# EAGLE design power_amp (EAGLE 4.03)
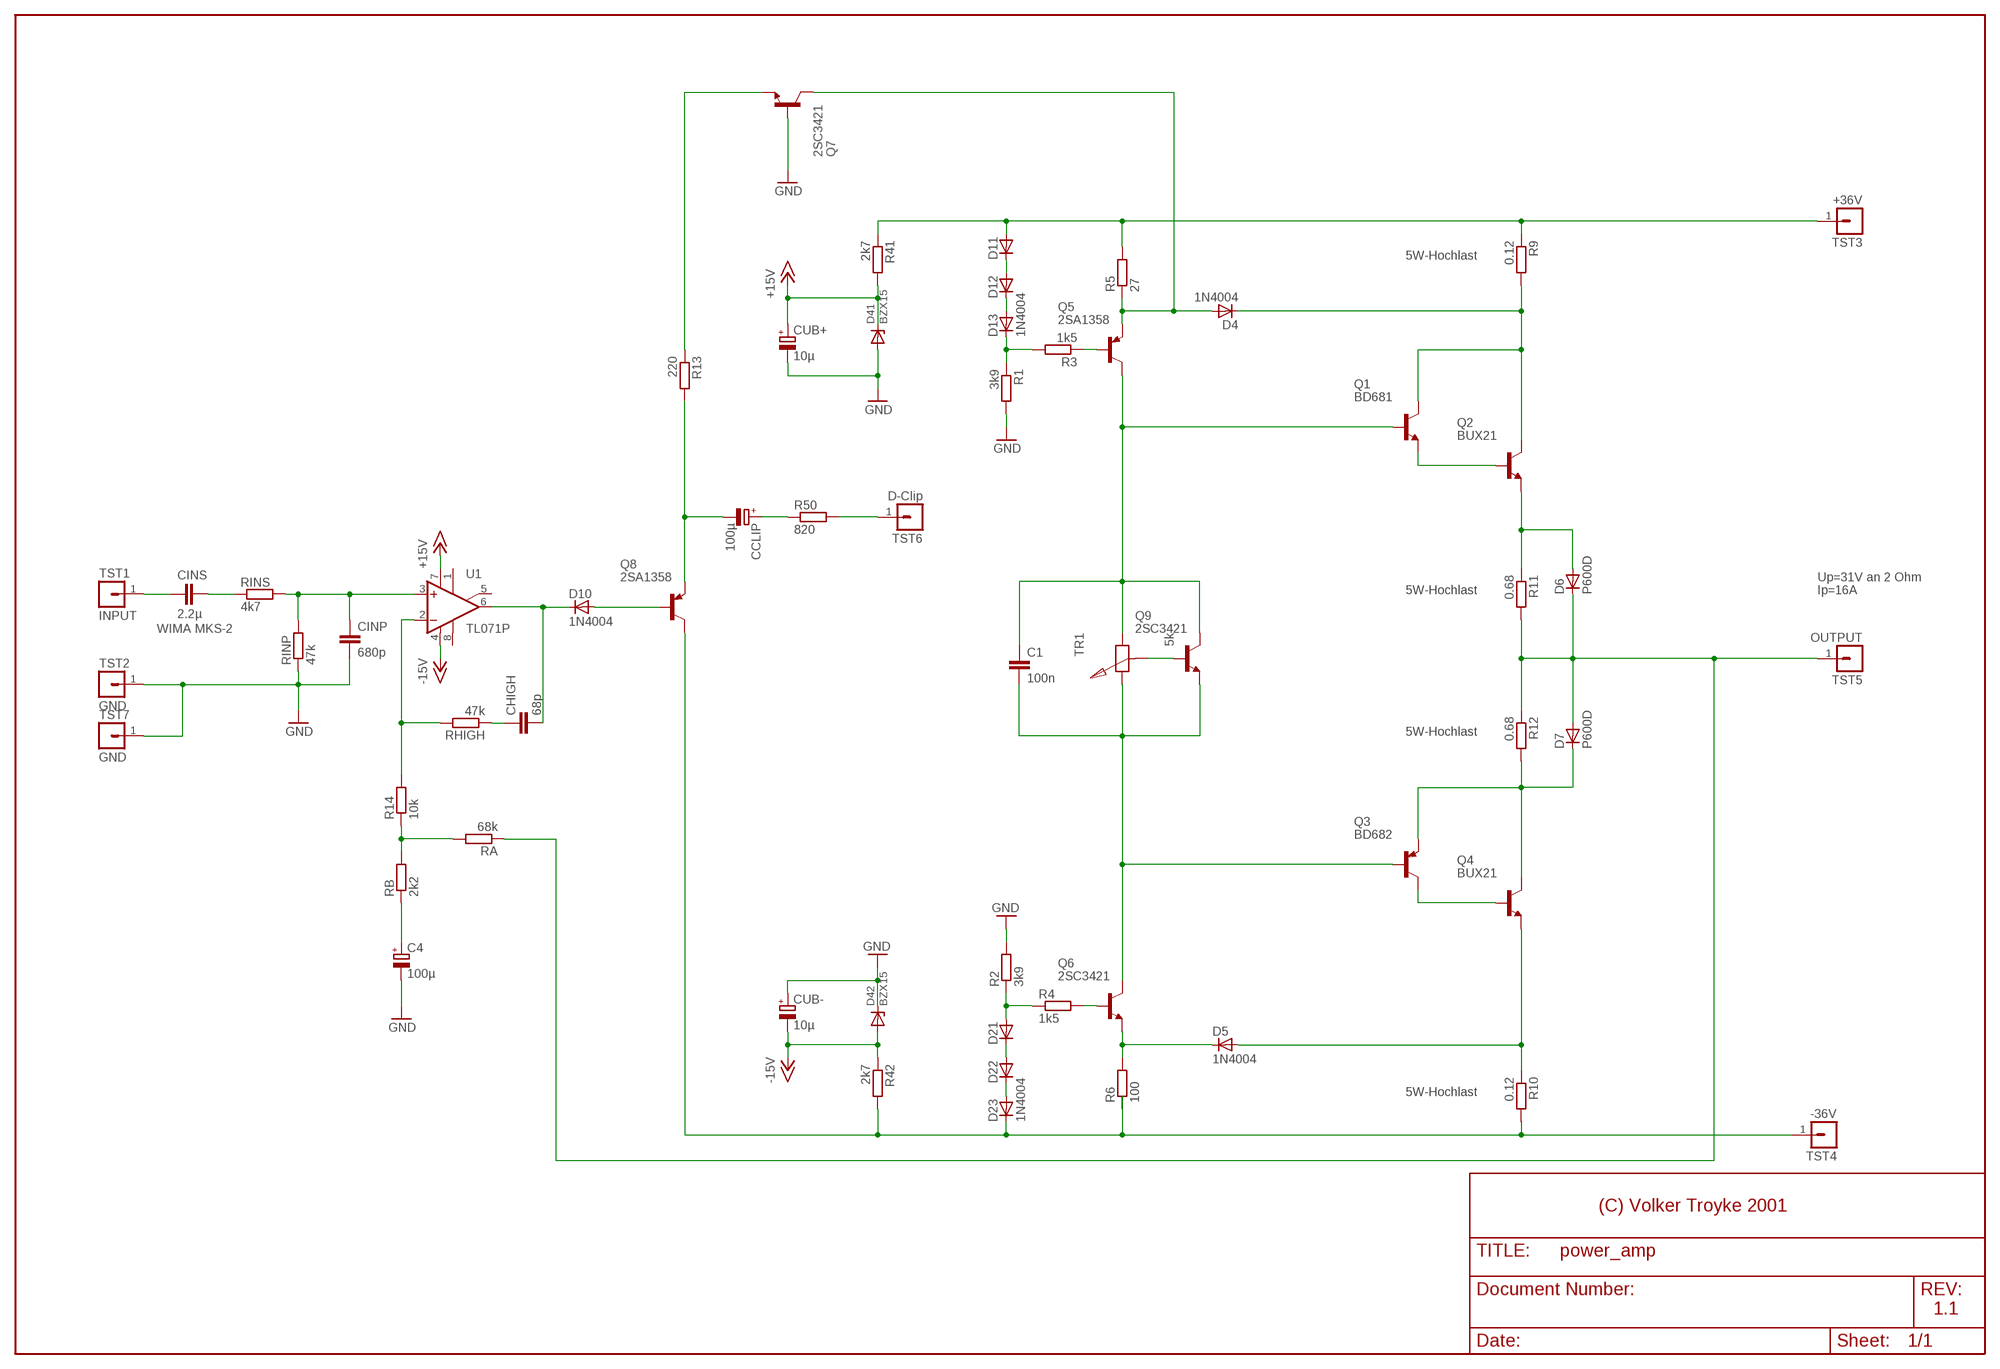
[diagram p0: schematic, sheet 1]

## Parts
C1  100n  C-EU050-024X044  [C050-024X044]
C4  100µ  CPOL-EUE2.5-7  [E2,5-7]
CCLIP  100µ  CPOL-EUE2.5-7  [E2,5-7]
CHIGH  68p  C-EU050-024X044  [C050-024X044]
CINP  680p  C-EU050-024X044  [C050-024X044]
CINS  2.2µ  C4PADS_LARGE  [C_40_L]
CUB+  10µ  CPOL-EUB45181B  [B45181B]
CUB-  10µ  CPOL-EUB45181B  [B45181B]
D4  1N4004  DSTEHEND  [D-STEHEND]
D5  1N4004  DSTEHEND  [D-STEHEND]
D6  P600D  DP600  [DIODE6A]
D7  P600D  DP600  [DIODE6A]
D10  1N4004  DSTEHEND  [D-STEHEND]
D11  DLIEGEND_7  [DO41-7]
D12  DLIEGEND_7  [DO41-7]
D13  1N4004  DLIEGEND_7  [DO41-7]
D21  DLIEGEND_7  [DO41-7]
D22  DLIEGEND_7  [DO41-7]
D23  1N4004  DLIEGEND_7  [DO41-7]
D41  BZX15  Z-DIODEBZX_7  [DO35Z7]
D42  BZX15  Z-DIODEBZX_7  [DO35Z7]
Q1  BD681  T-NPNBD  [TRANS_BD]
Q2  BUX21  T-NPNPOWER_INLINE  [TRANS_PWR]
Q3  BD682  T-PNPBD  [TRANS_BD]
Q4  BUX21  T-NPNPOWER_INLINE  [TRANS_PWR]
Q5  2SA1358  T-PNPBD  [TRANS_BD]
Q6  2SC3421  T-NPNBD  [TRANS_BD]
Q7  2SC3421  T-NPNBD  [TRANS_BD]
Q8  2SA1358  T-PNPBD  [TRANS_BD]
Q9  2SC3421  T-NPNBD  [TRANS_BD]
R1  3k9  R-EU_0207/2V  [0207/2V]
R2  3k9  R-EU_0207/2V  [0207/2V]
R3  1k5  R-EU_0207/2V  [0207/2V]
R4  1k5  R-EU_0207/2V  [0207/2V]
R5  27  R-EU_0207/2V  [0207/2V]
R6  100  R-EU_0207/2V  [0207/2V]
R9  0.12  R5W_STEHEND  [R5W_STEH]
R10  0.12  R5W_STEHEND  [R5W_STEH]
R11  0.68  R5W_STEHEND  [R5W_STEH]
R12  0.68  R5W_STEHEND  [R5W_STEH]
R13  220  R-EU_0207/2V  [0207/2V]
R14  10k  R-EU_0207/2V  [0207/2V]
R41  2k7  R-EU_0207/10  [0207/10]
R42  2k7  R-EU_0207/2V  [0207/2V]
R50  820  R-EU_0207/2V  [0207/2V]
RA  68k  R-EU_0207/10  [0207/10]
RB  2k2  R-EU_0207/2V  [0207/2V]
RHIGH  47k  R-EU_0207/2V  [0207/2V]
RINP  47k  R-EU_0207/10  [0207/10]
RINS  4k7  R-EU_0207/10  [0207/10]
TR1  5k  R-TRIMMGROSS  [STRIMMER1]
TST1  INPUT  TESTPINNORMAL  [TESTPAD]
TST2  GND  TESTPINNORMAL  [TESTPAD]
TST3  +36V  TESTPINGROSS  [TESTPAD_GROSS]
TST4  -36V  TESTPINGROSS  [TESTPAD_GROSS]
TST5  OUTPUT  TESTPINGROSS  [TESTPAD_GROSS]
TST6  D-Clip  TESTPINNORMAL  [TESTPAD]
TST7  GND  TESTPINNORMAL  [TESTPAD]
U1  TL071P  [DIL08]

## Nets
1-0: CINP.2 RINP.2 RINS.2 U1.3(+IN)
2-0: D6.K D7.A R11.2 R12.1 RA.1 TST5.1
3-0: R14.1 RA.2 RB.2
4-0: C4.+ RB.1
5-0: CHIGH.1 D10.K U1.6(OUT)
6-0: D10.A Q8.B
7-0: CCLIP.- Q8.E R13.2
8-0: Q7.E R13.1
9-0: D4.A Q5.E Q7.C R5.1
10-0: D11.K D12.A
11-0: D12.K D13.A
12-0: D13.K R1.1 R3.2
13-0: D4.K Q1.C Q2.C R9.2
14-0: C1.2 Q1.B Q5.C Q9.C TR1.1
15-0: Q1.E Q2.B
16-0: D6.A Q2.E R11.1
17-0: D7.K Q3.E Q4.C R12.2
18-0: Q3.C Q4.B
19-0: D5.A Q4.E R10.1
20-0: D5.K Q6.E R6.2
21-0: Q9.B TR1.3
23-0: C1.1 Q3.B Q6.C Q9.E TR1.2
24-0: Q6.B R4.2
25-0: D21.A R2.1 R4.1
26-0: D21.K D22.A
27-0: D22.K D23.A
30-0: R14.2 RHIGH.2 U1.2(-IN)
31-0: CHIGH.2 RHIGH.1
100-0: CINS.1 TST1.1
101-0: CINS.2 RINS.1
+15V: CUB+.+ D41.K R41.2 U1.7(V+)
+36V: D11.A R5.2 R9.1 R41.1 TST3.1
-15V: CUB-.- D42.A R42.1 U1.4(V-)
-36V: D23.K Q8.C R6.1 R10.2 R42.2 TST4.1
GND: C4.- CINP.1 CUB+.- CUB-.+ D41.A D42.K Q7.B R1.2 R2.2 RINP.1 TST2.1 TST7.1
N$18: Q5.B R3.1
N$23: CCLIP.+ R50.1
N$24: R50.2 TST6.1
Unconnected: U1.1(ON1) U1.5(ON2) U1.8(OPT)

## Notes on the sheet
- 5W-Hochlast
- Up=31V an 2 Ohm
- 5W-Hochlast | Ip=16A
- WIMA MKS-2
- 5W-Hochlast
- 5W-Hochlast
- (C) Volker Troyke 2001
- 1.1

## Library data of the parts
C1 CHIGH CINP = rcl:C-EU: CAPACITOR, European symbol
C4 CCLIP CUB+ CUB- = rcl:CPOL-EU: POLARIZED CAPACITOR, European symbol
CINS = VT:C: Kondensator
D4-D7 D10-D13 D21-D23 = VT:D: Diode
D41 D42 = VT:Z-DIODE: Z-Diode
Q1 Q2 Q4 Q6 Q7 Q9 = VT:T-NPN: Transistor NPN
Q3 Q5 Q8 = VT:T-PNP: Transistor PNP
R1-R6 R13 R14 R41 R42 R50 RA RB RHIGH RINP RINS = rcl:R-EU_: RESISTOR, European symbol
R9-R12 = VT:R: Widerstand
TR1 = VT:R-TRIMM: Spindeltrimmer
TST1-TST7 = VT:TESTPIN: Einzelpad
U1 = linear:TL071P: OP AMP

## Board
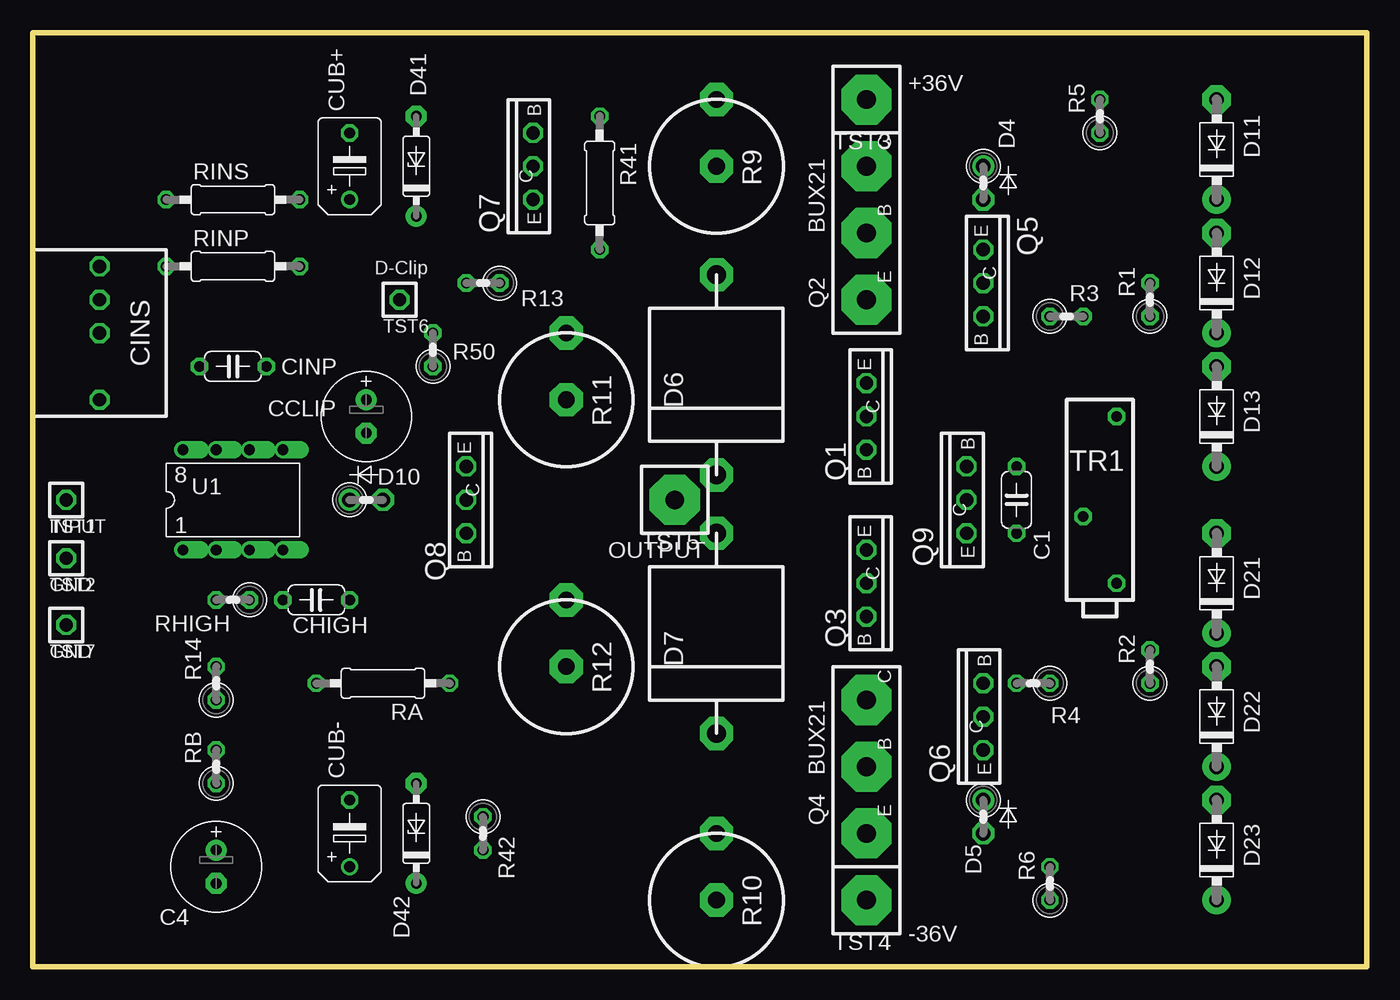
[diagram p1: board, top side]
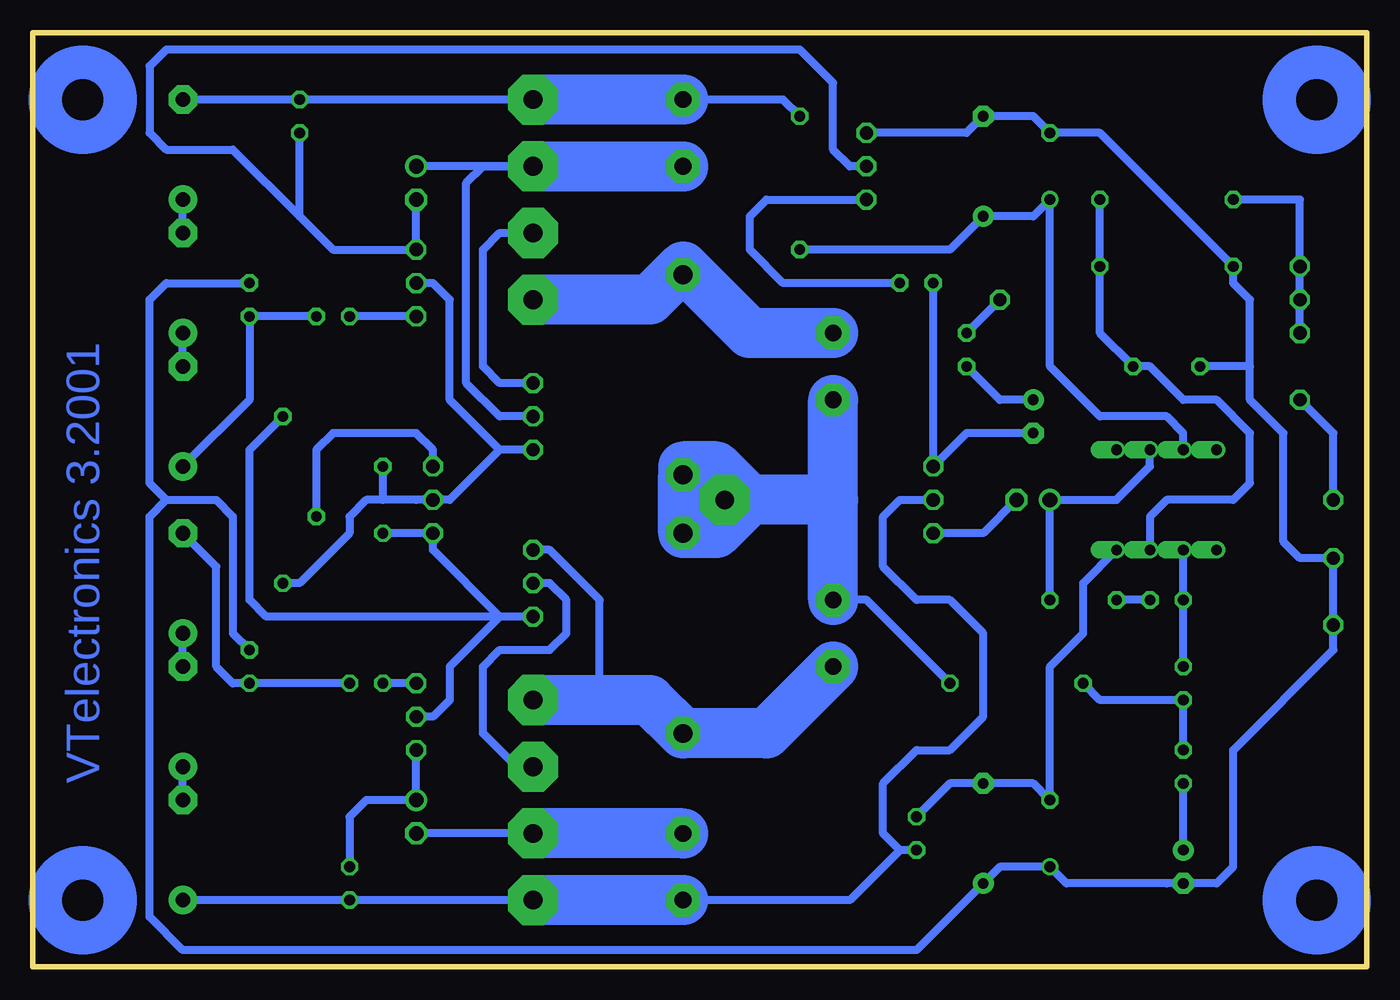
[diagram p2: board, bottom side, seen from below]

Size 101.6 x 71.12 mm. Coordinates in mm from the lower left corner, seen from the top.
Outline: 0,0 101.6,0 101.6,71.12 0,71.12 0,0
Copper layers used: Bottom

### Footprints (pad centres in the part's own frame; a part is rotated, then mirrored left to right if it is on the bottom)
C050-024X044 = drill 0.813 octagon: 1 -2.54,0; 2 2.54,0
E2,5-7 = drill 0.813 pad 1.6 round: + -1.27,0 | drill 0.813 pad 1.6 octagon: - 1.27,0
C_40_L = drill 1.016 octagon: 1 0,0; 2 5.08,0; 3 7.62,0; 4 10.16,0
B45181B = drill 0.813 round: + -2.54,0 | drill 0.813 octagon: - 2.54,0
D-STEHEND = drill 1.118 octagon: A 1.27,0 | drill 1.118 round: K -1.27,0
DIODE6A = drill 1.422 pad 2.54 octagon: A 7.62,0; K -7.62,0
DO41-7 = drill 1.118 pad 2.159 octagon: A 3.81,0 | drill 1.118 pad 2.159 round: K -3.81,0
DO35Z7 = drill 0.813 pad 1.6 octagon: A 3.81,0 | drill 0.813 pad 1.6 round: K -3.81,0
TRANS_BD = drill 1.016 octagon: B 2.54,0; C 0,0; E -2.54,0
TRANS_PWR = drill 1.422 pad 3.81 octagon: B 0,0; C 5.08,0; E -5.08,0
0207/2V = drill 0.813 octagon: 1 -1.27,0; 2 1.27,0
R5W_STEH = drill 1.27 pad 2.54 octagon: 1 -5.08,0; 2 0,0
0207/10 = drill 0.813 octagon: 1 -5.08,0; 2 5.08,0
STRIMMER1 = drill 0.813 octagon: 1 -1.27,6.35; 2 -1.27,-6.35; 3 1.27,1.27
TESTPAD = drill 1.016 octagon: 1 0,0
TESTPAD_GROSS = drill 1.422 pad 3.81 octagon: 1 0,0
DIL08 = drill 0.813 offset: 1 -3.81,-3.81; 2 -1.27,-3.81; 3 1.27,-3.81; 4 3.81,-3.81; 5 3.81,3.81; 6 1.27,3.81; 7 -1.27,3.81; 8 -3.81,3.81

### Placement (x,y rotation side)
C1  74.93,35.56 90 top
C4  13.97,7.62 270 top
CCLIP  25.4,41.91 270 top
CHIGH  21.59,27.94 180 top
CINP  15.24,45.72 0 top
CINS  5.08,43.18 90 top
CUB+  24.13,60.96 90 top
CUB-  24.13,10.16 90 top
D4  72.39,59.69 270 top
D5  72.39,11.43 270 top
D6  52.07,45.09 90 top
D7  52.07,25.4 90 top
D10  25.4,35.56 0 top
D11  90.17,62.23 90 top
D12  90.17,52.07 90 top
D13  90.17,41.91 90 top
D21  90.17,29.21 90 top
D22  90.17,19.05 90 top
D23  90.17,8.89 90 top
D41  29.21,60.96 90 top
D42  29.21,10.16 90 top
Q1  63.5,41.91 270 top
Q2  63.5,55.88 90 top
Q3  63.5,29.21 270 top
Q4  63.5,15.24 90 top
Q5  72.39,52.07 270 top
Q6  72.39,19.05 90 top
Q7  38.1,60.96 90 top
Q8  33.02,35.56 270 top
Q9  71.12,35.56 90 top
R1  85.09,50.8 90 top
R2  85.09,22.86 90 top
R3  78.74,49.53 0 top
R4  76.2,21.59 180 top
R5  81.28,64.77 90 top
R6  77.47,6.35 90 top
R9  52.07,60.96 270 top
R10  52.07,5.08 270 top
R11  40.64,43.18 270 top
R12  40.64,22.86 270 top
R13  34.29,52.07 180 top
R14  13.97,21.59 90 top
R41  43.18,59.69 270 top
R42  34.29,10.16 270 top
R50  30.48,46.99 90 top
RA  26.67,21.59 180 top
RB  13.97,15.24 90 top
RHIGH  15.24,27.94 180 top
RINP  15.24,53.34 0 top
RINS  15.24,58.42 0 top
TR1  81.28,35.56 180 top
TST1  2.54,35.56 0 top
TST2  2.54,31.11 0 top
TST3  63.5,66.04 0 top
TST4  63.5,5.08 0 top
TST5  48.9,35.56 0 top
TST6  27.94,50.8 0 top
TST7  2.54,26.04 0 top
U1  15.24,35.56 0 top

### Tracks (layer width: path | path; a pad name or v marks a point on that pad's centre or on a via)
1-0
  Bottom 0.61: U1.3 16.51,34.29 15.24,35.56 10.16,35.56 8.89,36.83 8.89,40.64 11.43,43.18 13.97,43.18 16.51,45.72 CINP.2 20.32,48.26 RINP.2 | RINP.2 RINS.2 RINP.2
2-0
  Bottom 0.61: RA.1 38.1,27.94 R12.1 | 49.53,35.56 50.16,35.56
  Bottom 3.81: 52.07,38.1 49.53,35.56 | 46.99,35.56 TST5.1 49.53,35.56 | D7.A 49.53,35.56 | 52.07,38.1 49.53,38.1 46.99,35.56 | D7.A 49.53,33.02 46.99,35.56 | D7.A D6.K 52.07,38.1 | R12.1 40.64,35.56 | 40.64,35.56 R11.2 | 40.64,35.56 46.99,35.56
3-0
  Bottom 0.61: RB.2 R14.1 20.32,20.32 RA.2
4-0
  Bottom 0.61: C4.+ RB.1
5-0
  Bottom 0.61: CHIGH.1 D10.K 19.05,35.56 16.51,38.1 U1.6
6-0
  Bottom 0.61: D10.A 29.21,33.02 Q8.B
7-0
  Bottom 0.61: R13.2 Q8.E 30.48,40.64 CCLIP.-
8-0
  Bottom 0.61: R13.1 44.45,52.07 46.99,54.61 46.99,57.15 45.72,58.42 Q7.E
9-0
  Bottom 0.61: D4.A Q5.E 78.74,54.61 81.28,57.15 | 81.28,57.15 R5.1 | 81.28,57.15 86.36,62.23 91.44,62.23 92.71,63.5 92.71,68.58 91.44,69.85 43.18,69.85 40.64,67.31 40.64,62.23 39.37,60.96 Q7.C
10-0
  Bottom 0.61: D12.A D11.K
11-0
  Bottom 0.61: D13.A D12.K
12-0
  Bottom 0.61: R3.2 R1.1 85.09,43.18 D13.K
13-0
  Bottom 0.61: Q1.C 66.04,41.91 68.58,44.45 68.58,59.69 67.31,60.96 Q2.C D4.K
  Bottom 3.81: Q2.C R9.2
14-0
  Bottom 0.61: Q5.C 71.12,52.07 69.85,50.8 69.85,43.18 66.04,39.37 | Q1.B 66.04,39.37 | Q9.C 72.39,35.56 | TR1.1 81.28,29.21 77.47,33.02 77.47,34.29 76.2,35.56 74.93,35.56 | Q9.C 74.93,35.56 | Q9.C 69.85,35.56 66.04,39.37 | 74.93,35.56 C1.2
15-0
  Bottom 0.61: Q1.E 66.04,44.45 67.31,45.72 67.31,54.61 66.04,55.88 Q2.B
16-0
  Bottom 0.61: 52.07,53.34 D6.A
  Bottom 3.81: Q2.E 54.61,50.8 52.07,53.34 46.99,48.26 R11.1
17-0
  Bottom 0.406: Q4.C 62.23,21.59
  Bottom 0.61: Q3.E 62.23,31.75 58.42,27.94 58.42,21.59 62.23,21.59
  Bottom 3.81: R12.2 45.72,17.78 D7.K 54.61,20.32 Q4.C
18-0
  Bottom 0.61: Q4.B 64.77,15.24 67.31,17.78 67.31,22.86 66.04,24.13 62.23,24.13 60.96,25.4 60.96,27.94 62.23,29.21 Q3.C
19-0
  Bottom 0.61: Q4.E D5.A
  Bottom 3.81: R10.1 Q4.E
20-0
  Bottom 0.61: Q6.E D5.K 76.2,12.7 77.47,11.43 R6.2
21-0
  Bottom 0.61: Q9.B 71.12,39.37 72.39,40.64 78.74,40.64 80.01,39.37 TR1.3
23-0
  Bottom 0.61: Q6.C 71.12,19.05 69.85,20.32 69.85,22.86 66.04,26.67 | Q3.B 66.04,26.67 | 66.04,26.67 71.12,31.75 Q9.E C1.1 | TR1.2 85.09,39.37 85.09,27.94 83.82,26.67 66.04,26.67
24-0
  Bottom 0.61: Q6.B R4.2
25-0
  Bottom 0.61: R4.1 R2.1 86.36,21.59 87.63,22.86 87.63,30.48 D21.A
26-0
  Bottom 0.61: D22.A D21.K
27-0
  Bottom 0.61: D23.A D22.K
30-0
  Bottom 0.61: R14.2 RHIGH.2 | RHIGH.2 U1.2 RHIGH.2
31-0
  Bottom 0.61: RHIGH.1 CHIGH.2
100-0
  Bottom 0.61: TST1.1 2.54,40.64 CINS.1
101-0
  Bottom 0.61: RINS.1 5.08,58.42 CINS.2
+15V
  Bottom 0.61: R41.2 31.75,54.61 D41.K 25.4,57.15 CUB+.+ 24.13,45.72 20.32,41.91 15.24,41.91 13.97,40.64 U1.7
+36V
  Bottom 0.61: TST3.1 R5.2 | R5.2 D11.A R5.2 | R41.1 44.45,66.04 R9.1
  Bottom 3.81: R9.1 TST3.1
-15V
  Bottom 0.61: R42.1 31.75,13.97 D42.A 25.4,13.97 CUB-.- 24.13,22.86 21.59,25.4 21.59,29.21 U1.4
-36V
  Bottom 0.61: TST4.1 R6.1 | R6.1 D23.K R6.1 | Q8.C 35.56,35.56 36.83,34.29 36.83,30.48 34.29,27.94 31.75,27.94 29.21,25.4 29.21,19.05 31.75,16.51 34.29,16.51 36.83,13.97 36.83,10.16 35.56,8.89 | R42.2 35.56,8.89 | 35.56,8.89 39.37,5.08 R10.2
  Bottom 3.81: R10.2 TST4.1
GND
  Bottom 0.61: R1.2 91.44,52.07 92.71,50.8 92.71,36.83 91.44,35.56 | R2.2 86.36,25.4 86.36,34.29 87.63,35.56 91.44,35.56 | 91.44,35.56 92.71,34.29 92.71,3.81 90.17,1.27 34.29,1.27 D42.K 27.94,7.62 CUB-.+ 22.86,6.35 C4.- | C4.- 15.24,6.35 | Q7.B 30.48,63.5 D41.A 25.4,64.77 CUB+.- 20.32,63.5 RINP.1 10.16,52.07 8.89,50.8 8.89,45.72 | 8.89,45.72 CINP.1 | 8.89,45.72 8.89,43.18 6.35,40.64 6.35,32.38 5.08,31.11 TST2.1 TST7.1 2.54,24.13 10.16,16.51 10.16,7.62 11.43,6.35 C4.-
N$18
  Bottom 0.61: Q5.B R3.1
N$23
  Bottom 0.61: CCLIP.+ 27.94,43.18 R50.1
N$24
  Bottom 0.61: TST6.1 R50.2
(copper drawn outside any net)
  shapes: Bottom circle x4

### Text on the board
Bottom: VTelectronics 3.2001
